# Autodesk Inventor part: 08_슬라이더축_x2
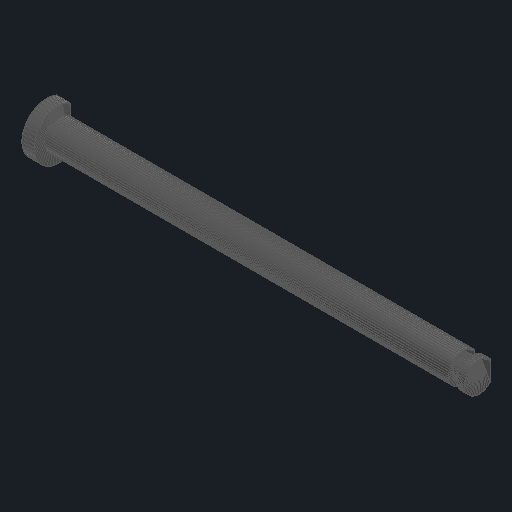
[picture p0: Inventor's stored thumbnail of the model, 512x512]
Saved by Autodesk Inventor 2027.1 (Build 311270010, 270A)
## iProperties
Created: 2026-11
Part Number: 08_슬라이더축_x2
Material: 일반
Document SubType Name: Modeling
Designer: djshs
Density: 1 g/cm^3
Appearance: 기본값
Author: djshs
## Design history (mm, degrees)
node "08_슬라이더축_x2"
  node "MeshFeature1"
